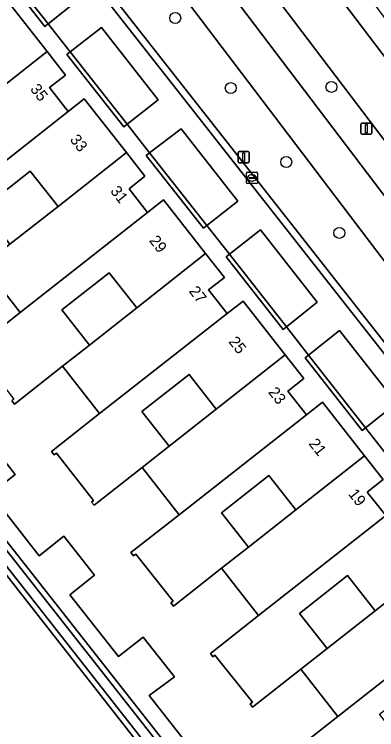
# Model space of a CAD drawing. Extents: x 156661 to 157576, y 383570 to 384425.
# Drawn here: x 157004.6 to 157036.8, y 383983.3 to 384046.8 of the extents above; entities that cross this region are included whole.
import ezdxf

# ---------------------------------------------------------------- set-up
doc = ezdxf.new("R2010")
doc.units = 0
for name, color, linetype in [('IMGEO_Berm_groen', 7, 'Continuous'), ('IMGEO_Boom', 7, 'Continuous'), ('IMGEO_Erf', 7, 'Continuous'), ('IMGEO_Fietspad_gesloten', 7, 'Continuous'), ('IMGEO_Groenvoorziening', 7, 'Continuous'), ('IMGEO_Kolk', 7, 'Continuous'), ('IMGEO_Lichtmast', 7, 'Continuous'), ('IMGEO_Muur', 7, 'Continuous'), ('IMGEO_Oever', 7, 'Continuous'), ('IMGEO_Pand', 7, 'Continuous'), ('IMGEO_Pand_nummerreeks', 7, 'Continuous'), ('IMGEO_Parkeervlak_open', 7, 'Continuous'), ('IMGEO_Rijbaan_lokaal_open', 7, 'Continuous'), ('IMGEO_Voetpad_gesloten', 7, 'Continuous'), ('IMGEO_Voetpad_open', 7, 'Continuous'), ('IMGEO_Waterloop', 7, 'Continuous')]:
    doc.layers.add(name, color=color, linetype=linetype)

msp = doc.modelspace()

# ---------------------------------------------------------------- linework, layer by layer
at = {"layer": 'IMGEO_Berm_groen'}
for points in [[(157022.83, 384054.925), (157020.102, 384058.503), (157014.424, 384065.95), (157012.072, 384064.137), (157061.136, 383999.546), (157065.088, 383994.36), (157067.449, 383996.186), (157062.167, 384003.14)], [(157009.29, 384061.994), (157005.166, 384058.77), (157059.34, 383989.875), (157062.312, 383992.226)]]:
    msp.add_lwpolyline(points, close=True, dxfattribs=at)
at = {"layer": 'IMGEO_Boom'}
for centre in [(157018.868, 384046.493), (157023.808, 384040.274), (157032.753, 384040.379), (157028.73, 384033.718), (157033.457, 384027.42)]:
    msp.add_circle(centre, 0.489, dxfattribs=at)
at = {"layer": 'IMGEO_Erf'}
for points in [[(157037.743, 384007.639), (157035.789, 384010.121), (157035.483, 384009.88), (157030.406, 384016.34), (157030.713, 384016.581), (157028.759, 384019.077), (157028.46, 384018.842), (157023.383, 384025.302), (157023.681, 384025.537), (157021.669, 384028.075), (157021.37, 384027.84), (157016.293, 384034.3), (157016.591, 384034.535), (157014.612, 384037.061), (157014.314, 384036.826), (157009.25, 384043.265), (157009.548, 384043.5), (157007.572, 384045.986), (157007.272, 384045.751), (157004.87, 384048.821)], [(157003.893, 384048.068), (157007.481, 384043.516), (157009.125, 384041.431), (157007.711, 384040.317), (157009.36, 384038.209), (157010.774, 384039.323), (157014.527, 384034.557), (157016.181, 384032.458), (157014.767, 384031.344), (157016.411, 384029.241), (157017.826, 384030.353), (157021.571, 384025.59), (157023.24, 384023.467), (157021.826, 384022.355), (157023.492, 384020.253), (157024.908, 384021.365), (157028.643, 384016.605), (157030.298, 384014.497), (157028.882, 384013.386), (157030.531, 384011.288), (157031.946, 384012.401), (157035.684, 384007.648), (157037.347, 384005.534), (157035.932, 384004.421), (157037.584, 384002.328)], [(157000.838, 384016.991), (157005.1, 384020.364), (157001.809, 384024.548)], [(157029.036, 383981.139), (157033.325, 383984.498), (157030.022, 383988.688), (157025.745, 383985.318), (157025.516, 383985.608), (157025.728, 383985.775), (157022.401, 383989.945), (157022.216, 383989.804), (157021.992, 383990.098), (157026.276, 383993.464), (157022.984, 383997.653), (157018.702, 383994.289), (157018.474, 383994.58), (157018.686, 383994.747), (157015.357, 383998.916), (157015.167, 383998.769), (157014.938, 383999.048), (157019.216, 384002.403), (157015.928, 384006.599), (157011.652, 384003.247), (157011.422, 384003.533), (157011.604, 384003.679), (157008.319, 384007.878), (157008.127, 384007.735), (157007.885, 384008.026), (157012.149, 384011.38), (157008.851, 384015.58), (157004.584, 384012.23), (157004.356, 384012.521)], [(157001.889, 384009.491), (157004.648, 384005.987), (157002.448, 384004.255), (157006.765, 383998.77), (157008.965, 384000.502), (157011.7, 383997.029), (157009.5, 383995.297), (157013.816, 383989.813), (157016.016, 383991.544), (157018.799, 383988.01), (157016.54, 383986.353), (157020.868, 383980.855)]]:
    msp.add_lwpolyline(points, dxfattribs=at)
for points in [[(157008.454, 384029.777), (157005.992, 384032.905), (157001.723, 384029.546), (157004.185, 384026.418)], [(157015.454, 384020.776), (157013.006, 384023.886), (157008.804, 384020.579), (157011.251, 384017.469)], [(157018.317, 384008.479), (157022.515, 384011.782), (157020.094, 384014.858), (157015.896, 384011.555)], [(157025.375, 383999.535), (157029.582, 384002.846), (157027.185, 384005.892), (157022.978, 384002.582)], [(157032.369, 383990.535), (157036.625, 383993.885), (157034.175, 383996.998), (157029.919, 383993.648)]]:
    msp.add_lwpolyline(points, close=True, dxfattribs=at)
at = {"layer": 'IMGEO_Fietspad_gesloten'}
for points in [[(156992.1, 384084.489), (156997.679, 384077.272), (157008.067, 384063.603), (157009.29, 384061.994), (157062.312, 383992.226), (157063.404, 383990.789), (157089.259, 383956.768)], [(157092.711, 383958.119), (157066.152, 383992.965), (157065.088, 383994.36), (157061.136, 383999.546), (157012.072, 384064.137)]]:
    msp.add_lwpolyline(points, dxfattribs=at)
at = {"layer": 'IMGEO_Groenvoorziening'}
for points in [[(157004.997, 384049.272), (157007.572, 384045.986), (157010.319, 384048.193)], [(156977.044, 384038.227), (156977.796, 384037.236), (156980.256, 384030.02), (157001.17, 384003.466), (157046.683, 383945.676)], [(157046.683, 383945.676), (157050.688, 383940.493), (157051.572, 383939.133), (157065.473, 383940.297), (157066.12, 383939.807), (157065.553, 383939.239), (157051.199, 383938.08), (157049.143, 383939.851), (157046.243, 383943.057), (156999.575, 384002.48), (156979.971, 384027.441), (156979.057, 384027.27), (156978.106, 384028.607), (156978.828, 384029.096), (156976.159, 384036.79), (156976.265, 384037.915)], [(157020.868, 383980.855), (157016.54, 383986.353), (157018.799, 383988.01), (157016.016, 383991.544), (157013.816, 383989.813), (157009.5, 383995.297), (157011.7, 383997.029), (157008.965, 384000.502), (157006.765, 383998.77), (157002.448, 384004.255), (157004.648, 384005.987), (157001.889, 384009.491)]]:
    msp.add_lwpolyline(points, dxfattribs=at)
for points in [[(157012.327, 384045.659), (157009.548, 384043.5), (157014.612, 384037.061), (157017.349, 384039.223)], [(157019.389, 384036.672), (157016.591, 384034.535), (157021.669, 384028.075), (157024.426, 384030.242)], [(157026.451, 384027.686), (157023.681, 384025.537), (157028.759, 384019.077), (157031.489, 384021.286)], [(157033.481, 384018.753), (157030.713, 384016.581), (157035.789, 384010.121), (157038.54, 384012.322)]]:
    msp.add_lwpolyline(points, close=True, dxfattribs=at)
at = {"layer": 'IMGEO_Kolk'}
for p, q in [((157025.19, 384031.878), (157025.19, 384032.73)), ((157025.265, 384032.804), (157026.117, 384032.804)), ((157025.678, 384032.584), (157025.703, 384032.584)), ((157026.191, 384032.73), (157026.191, 384031.878)), ((157026.117, 384031.804), (157025.265, 384031.804)), ((157025.449, 384032.298), (157025.449, 384032.31)), ((157025.887, 384032.261), (157025.489, 384032.261)), ((157025.492, 384032.347), (157025.89, 384032.347)), ((157025.701, 384032.024), (157025.676, 384032.024)), ((157025.933, 384032.31), (157025.933, 384032.298))]:
    msp.add_line(p, q, dxfattribs=at)
for points in [[(157025.19, 384031.878), (157025.19, 384032.73)], [(157025.265, 384032.804), (157026.117, 384032.804)], [(157026.191, 384032.73), (157026.191, 384031.878)], [(157026.117, 384031.804), (157025.265, 384031.804)]]:
    msp.add_lwpolyline(points, dxfattribs=at)
for centre, radius, start, end in [((157025.267, 384032.728), 0.0765, 91.55205, 178.44795), ((157025.267, 384032.728), 0.0765, 91.55205, 178.44795), ((157026.115, 384032.728), 0.0765, 1.55205, 88.44795), ((157026.115, 384032.728), 0.0765, 1.55205, 88.44795), ((157025.267, 384031.88), 0.0765, 181.55205, 268.44795), ((157025.267, 384031.88), 0.0765, 181.55205, 268.44795), ((157025.489, 384032.307), 0.0403, 85.87752, 175.75265), ((157025.486, 384032.297), 0.0366, 178.93798, 274.71019), ((157025.89, 384032.304), 0.043, 264.86636, 352.45326), ((157025.894, 384032.309), 0.0386, 1.73085, 96.63898), ((157026.115, 384031.88), 0.0765, 271.55205, 358.44795), ((157026.115, 384031.88), 0.0765, 271.55205, 358.44795)]:
    msp.add_arc(centre, radius, start, end, dxfattribs=at)
for centre, major_axis, ratio, start_param, end_param in [((157025.677, 384032.304), (-0.387, 0.002), 0.722429, 4.712389, 7.853982), ((157025.702, 384032.304), (-0.39, 0.002), 0.717154, 1.570796, 4.712389)]:
    msp.add_ellipse(centre, major_axis=major_axis, ratio=ratio, start_param=start_param, end_param=end_param, dxfattribs=at)
at = {"layer": 'IMGEO_Lichtmast'}
for p, q in [((157035.355, 384036.271), (157035.355, 384037.071)), ((157035.355, 384037.071), (157035.355, 384036.271)), ((157035.455, 384037.171), (157036.245, 384037.171)), ((157036.245, 384037.171), (157035.455, 384037.171)), ((157036.345, 384037.071), (157036.345, 384036.271)), ((157036.345, 384036.271), (157036.345, 384037.071)), ((157036.245, 384036.171), (157035.455, 384036.171)), ((157035.455, 384036.171), (157036.245, 384036.171)), ((157024.454, 384033.744), (157024.454, 384034.544)), ((157024.454, 384034.544), (157024.454, 384033.744)), ((157024.554, 384034.644), (157025.344, 384034.644)), ((157025.344, 384034.644), (157024.554, 384034.644)), ((157025.444, 384034.544), (157025.444, 384033.744)), ((157025.444, 384033.744), (157025.444, 384034.544)), ((157025.344, 384033.644), (157024.554, 384033.644)), ((157024.554, 384033.644), (157025.344, 384033.644))]:
    msp.add_line(p, q, dxfattribs=at)
for points in [[(157035.775, 384037.046), (157035.925, 384037.046), (157035.925, 384036.296), (157035.775, 384036.296), (157035.775, 384037.046)], [(157024.874, 384034.519), (157025.024, 384034.519), (157025.024, 384033.769), (157024.874, 384033.769), (157024.874, 384034.519)]]:
    msp.add_lwpolyline(points, dxfattribs=at)
for centre, start, end in [((157035.455, 384037.071), 90, 180), ((157035.455, 384037.071), 90, 180), ((157036.245, 384037.071), 0, 90), ((157036.245, 384037.071), 360, 90), ((157035.455, 384036.271), 180, 270), ((157035.455, 384036.271), 180, 270), ((157036.245, 384036.271), 270, 0), ((157036.245, 384036.271), 270, 0), ((157024.554, 384034.544), 90, 180), ((157024.554, 384034.544), 90, 180), ((157025.344, 384034.544), 0, 90), ((157025.344, 384034.544), 360, 90), ((157024.554, 384033.744), 180, 270), ((157024.554, 384033.744), 180, 270), ((157025.344, 384033.744), 270, 0), ((157025.344, 384033.744), 270, 0)]:
    msp.add_arc(centre, 0.1, start, end, dxfattribs=at)
at = {"layer": 'IMGEO_Muur'}
for points in [[(157004.87, 384048.821), (157007.272, 384045.751), (157007.572, 384045.986), (157004.997, 384049.272), (157003.727, 384048.278), (157003.893, 384048.068)], [(157009.548, 384043.5), (157009.25, 384043.265), (157014.314, 384036.826), (157014.612, 384037.061)], [(157016.591, 384034.535), (157016.293, 384034.3), (157021.37, 384027.84), (157021.669, 384028.075)], [(157023.681, 384025.537), (157023.383, 384025.302), (157028.46, 384018.842), (157028.759, 384019.077)], [(157030.713, 384016.581), (157030.406, 384016.34), (157035.483, 384009.88), (157035.789, 384010.121)]]:
    msp.add_lwpolyline(points, close=True, dxfattribs=at)
at = {"layer": 'IMGEO_Oever'}
for points in [[(156976.265, 384037.915), (156976.159, 384036.79), (156978.828, 384029.096), (156978.106, 384028.607), (156979.057, 384027.27), (156979.971, 384027.441), (156999.575, 384002.48), (157046.243, 383943.057), (157049.143, 383939.851), (157051.199, 383938.08), (157065.553, 383939.239), (157066.12, 383939.807), (157065.473, 383940.297), (157051.572, 383939.133), (157050.688, 383940.493), (157046.683, 383945.676), (157001.17, 384003.466), (156980.256, 384030.02)], [(157046.629, 383943.382), (157028.661, 383966.26), (157028.063, 383967.022), (156999.971, 384002.791), (156999.39, 384003.532), (156998.793, 384004.292), (156980.179, 384027.993), (156979.281, 384027.825), (156978.816, 384028.479), (156979.431, 384028.896), (156976.671, 384036.852), (156976.758, 384037.771), (156977.345, 384036.996), (156979.807, 384029.776), (156999.461, 384004.822), (157000.061, 384004.06), (157000.774, 384003.154), (157028.774, 383967.601), (157029.374, 383966.839), (157046.286, 383945.366)]]:
    msp.add_lwpolyline(points, dxfattribs=at)
at = {"layer": 'IMGEO_Pand'}
for points in [[(157007.481, 384043.516), (157003.893, 384048.068), (157003.727, 384048.278), (157001.811, 384046.772), (156997.689, 384043.534), (157000.039, 384040.545), (156995.842, 384037.259), (156993.501, 384040.241), (156986.75, 384034.925), (156986.976, 384034.645), (156987.127, 384034.757), (156990.419, 384030.565), (156990.269, 384030.444), (156990.5, 384030.16), (156994.777, 384033.519)], [(156998.075, 384029.328), (157009.36, 384038.209), (157007.711, 384040.317), (157009.125, 384041.431), (157007.481, 384043.516), (156994.777, 384033.519)], [(157008.454, 384029.777), (157014.527, 384034.557), (157010.774, 384039.323), (157009.36, 384038.209), (156998.075, 384029.328), (156993.785, 384025.948), (156994.004, 384025.667), (156994.178, 384025.801), (156997.48, 384021.606), (156997.312, 384021.472), (156997.539, 384021.19), (157001.809, 384024.548), (157004.185, 384026.418), (157001.723, 384029.546), (157005.992, 384032.905)], [(157016.411, 384029.241), (157014.767, 384031.344), (157016.181, 384032.458), (157014.527, 384034.557), (157008.454, 384029.777), (157004.185, 384026.418), (157001.809, 384024.548), (157005.1, 384020.364)], [(157015.454, 384020.776), (157021.571, 384025.59), (157017.826, 384030.353), (157016.411, 384029.241), (157005.1, 384020.364), (157000.838, 384016.991), (157001.048, 384016.707), (157001.235, 384016.851), (157004.538, 384012.654), (157004.356, 384012.521), (157004.584, 384012.23), (157008.851, 384015.58), (157011.251, 384017.469), (157008.804, 384020.579), (157013.006, 384023.886)], [(157023.492, 384020.253), (157021.826, 384022.355), (157023.24, 384023.467), (157021.571, 384025.59), (157015.454, 384020.776), (157011.251, 384017.469), (157008.851, 384015.58), (157012.149, 384011.38)], [(157022.515, 384011.782), (157028.643, 384016.605), (157024.908, 384021.365), (157023.492, 384020.253), (157012.149, 384011.38), (157007.885, 384008.026), (157008.127, 384007.735), (157008.319, 384007.878), (157011.604, 384003.679), (157011.422, 384003.533), (157011.652, 384003.247), (157015.928, 384006.599), (157018.317, 384008.479), (157015.896, 384011.555), (157020.094, 384014.858)], [(157030.531, 384011.288), (157028.882, 384013.386), (157030.298, 384014.497), (157028.643, 384016.605), (157022.515, 384011.782), (157018.317, 384008.479), (157015.928, 384006.599), (157019.216, 384002.403)], [(157029.582, 384002.846), (157035.684, 384007.648), (157031.946, 384012.401), (157030.531, 384011.288), (157019.216, 384002.403), (157014.938, 383999.048), (157015.167, 383998.769), (157015.357, 383998.916), (157018.686, 383994.747), (157018.474, 383994.58), (157018.702, 383994.289), (157022.984, 383997.653), (157025.375, 383999.535), (157022.978, 384002.582), (157027.185, 384005.892)], [(157037.584, 384002.328), (157035.932, 384004.421), (157037.347, 384005.534), (157035.684, 384007.648), (157029.582, 384002.846), (157025.375, 383999.535), (157022.984, 383997.653), (157026.276, 383993.464)], [(157036.625, 383993.885), (157042.733, 383998.692), (157038.999, 384003.44), (157037.584, 384002.328), (157026.276, 383993.464), (157021.992, 383990.098), (157022.216, 383989.804), (157022.401, 383989.945), (157025.728, 383985.775), (157025.516, 383985.608), (157025.745, 383985.318), (157030.022, 383988.688), (157032.369, 383990.535), (157029.919, 383993.648), (157034.175, 383996.998)], [(157044.634, 383993.37), (157042.978, 383995.469), (157044.393, 383996.581), (157042.733, 383998.692), (157036.625, 383993.885), (157032.369, 383990.535), (157030.022, 383988.688), (157033.325, 383984.498)], [(157043.672, 383984.868), (157049.803, 383989.693), (157046.041, 383994.477), (157044.634, 383993.37), (157033.325, 383984.498), (157029.036, 383981.139), (157029.261, 383980.846), (157029.468, 383981.005), (157032.788, 383976.809), (157032.568, 383976.652), (157032.805, 383976.321), (157037.106, 383979.7), (157039.483, 383981.571), (157037.01, 383984.714), (157041.198, 383988.011)]]:
    msp.add_lwpolyline(points, close=True, dxfattribs=at)
at = {"layer": 'IMGEO_Parkeervlak_open'}
msp.add_lwpolyline([(157034.658, 384050.365), (157033.681, 384051.62), (157023.476, 384064.922), (157021.082, 384064.634), (157025.037, 384059.437), (157033.137, 384048.791), (157042.601, 384036.329), (157044.213, 384037.466)], close=True, dxfattribs=at)
at = {"layer": 'IMGEO_Rijbaan_lokaal_open'}
for points in [[(157022.83, 384054.925), (157062.167, 384003.14)], [(157042.601, 384036.329), (157033.137, 384048.791)]]:
    msp.add_lwpolyline(points, dxfattribs=at)
at = {"layer": 'IMGEO_Voetpad_gesloten'}
msp.add_lwpolyline([(157093.064, 383945.973), (157004.709, 384058.354), (157003.279, 384057.226), (157010.319, 384048.193), (157007.572, 384045.986), (157009.548, 384043.5), (157012.327, 384045.659), (157017.349, 384039.223), (157014.612, 384037.061), (157016.591, 384034.535), (157019.389, 384036.672), (157024.426, 384030.242), (157021.669, 384028.075), (157023.681, 384025.537), (157026.451, 384027.686), (157031.489, 384021.286), (157028.759, 384019.077), (157030.713, 384016.581), (157033.481, 384018.753), (157038.54, 384012.322), (157035.789, 384010.121), (157037.743, 384007.639)], dxfattribs=at)
at = {"layer": 'IMGEO_Voetpad_open'}
msp.add_lwpolyline([(157059.34, 383989.875), (157005.166, 384058.77), (157004.709, 384058.354), (157093.064, 383945.973), (157093.57, 383946.344), (157060.448, 383988.467)], close=True, dxfattribs=at)
at = {"layer": 'IMGEO_Waterloop'}
msp.add_lwpolyline([(157046.286, 383945.366), (157029.374, 383966.839), (157028.774, 383967.601), (157000.774, 384003.154), (157000.061, 384004.06), (156999.461, 384004.822), (156979.807, 384029.776), (156977.345, 384036.996), (156976.758, 384037.771), (156976.671, 384036.852), (156979.431, 384028.896), (156978.816, 384028.479), (156979.281, 384027.825), (156980.179, 384027.993), (156998.793, 384004.292), (156999.39, 384003.532), (156999.971, 384002.791), (157028.063, 383967.022), (157028.661, 383966.26), (157046.629, 383943.382)], dxfattribs=at)

# ---------------------------------------------------------------- texts
at = {"layer": 'IMGEO_Pand_nummerreeks'}
for s, rotation, p in [('35', 308.18175, (157005.929, 384040.172)), ('33', 308.1817, (157009.456, 384035.688)), ('31', 308.1817, (157013.05, 384031.117)), ('29', 308.1817, (157016.507, 384026.722)), ('27', 308.1817, (157020.035, 384022.236)), ('25', 308.1817, (157023.561, 384017.752)), ('23', 308.1817, (157027.087, 384013.268)), ('21', 308.1817, (157030.682, 384008.697)), ('19', 308.1817, (157034.194, 384004.23))]:
    msp.add_text(s, height=1, rotation=rotation, dxfattribs=at).set_placement(p)

doc.saveas('drawing.dxf')
